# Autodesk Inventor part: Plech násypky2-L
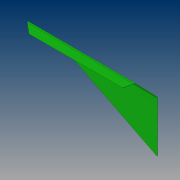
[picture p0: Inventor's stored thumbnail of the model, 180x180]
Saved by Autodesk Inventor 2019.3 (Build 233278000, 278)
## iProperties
Created: 2019-02
Part Number: Plech násypky2-L
Material: Ocel, legovaná
Document SubType Name: Plech
Designer: B-hon
Density: 7.73 g/cm^3
Sheet Metal Rule: Výchozí_mm
Appearance: Tmavě zelená
Author: B-hon
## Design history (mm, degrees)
node "Plocha1"
  sketch "Náčrt1"
    geometry: L1 (0, 0)-(380, 0); L2 (380, 0)-(380, 399.046); L3 (380, 399.046)-(0, 399.046); L4 (0, 399.046)-(0, 0)
    constraints: 8 end point, 2 parallel, 1 horizontal, 1 perpendicular
    dimensions: "d0" = 380 distance of L3.end L2.end
node "Obruba3"
sketch "Náčrt9"
  geometry: L1 (0, 0)-(380, 0) reference; L2 (380, 0)-(355.9, -113.384); L3 (0, -113.384)-(380, -113.384) reference; L4 (380, 0)-(380, -113.384) reference; 1 further point
  constraints: 2 end point, 1 point on line
  dimensions: "d55" = 12 deg angle of L4 L2
extrude "Vysunutí5" cut sketch "Náčrt9" distance "d56" = 10; taper "d57" = 0 deg
sketch "Náčrt10"
  geometry: L1 (-24.1, 400.209)-(0, 400.209) reference; L2 (-380, 400.209)-(-24.1, 400.209) reference; L3 (-24.1, 400.209)-(-510.684, 153.671); L4 (-510.205, 151.672)-(-426.211, -198.903); L5 (-426.211, -198.903)-(304.747, -58.027); L6 (304.747, -58.027)-(0, 400.209); L7 (-510.205, 151.672)-(-19.675, 400.209); 1 further point
  constraints: 10 end point, 1 parallel, 1 point on line
  dimensions: "d58" = 26.87 deg angle of L2 L3; "d83" = 2 distance between parallel lines of L3 L7
node "Upravit přímo3"
node "Upravit přímo4"
node "Obruba4"
extrude "Vysunutí8" cut sketch "Náčrt10" distance "d84" = 10; taper "d85" = 0 deg
node "Upravit přímo5"
node "Upravit přímo6"
sketch "Náčrt12"
  geometry: L1 (0, 0)-(0, 23); L2 (0, 21)-(0, 0) reference; L3 (352.406, 0)-(0, 0) reference; L4 (352.406, 0)-(352.406, 13.732); L5 (352.406, 21)-(352.406, 0) reference; L6 (371.519, 32.844)-(331.383, -7.291); L7 (331.383, -7.291)-(388.224, -9.134); L8 (388.224, -9.134)-(371.519, 32.844); L9 (-7.536, 30.536)-(34.31, -11.31); L10 (34.31, -11.31)-(-10.239, -14.013); L11 (-10.239, -14.013)-(-7.536, 30.536); L12 (0.85, 25)-(361.674, 25) reference; L13 (361.674, 21)-(361.674, 25) reference; 2 further points
  constraints: 16 end point, 3 point on line, 2 collinear, 1 midpoint
  dimensions: "d77" = 23 distance of L1.start L1.end; "d79" = 45 deg angle of L3 L9; "d80" = 45 deg angle of L3 L6; "d92" = 2 distance from line of L12 point (361.674, 23)
extrude "Vysunutí9" cut sketch "Náčrt12" distance "d93" = 6; taper "d94" = 0 deg
node "Těleso1"
feature "Deska1" dims "d1" = 2 (= Tloušťka)
sketch "Náčrt8"
  geometry: L1 through (-190, 0) direction (1, 0); L2 through (0, 57.5) direction (0, 1); L3 (0, 115)-(-380, 115); L4 (-380, 115)-(-380, 0)
  constraints: 6 end point, 1 horizontal, 1 perpendicular, 1 vertical
feature "Deska4" dims "d1" = 2 (= Tloušťka), "d45" = 2 (= ŠířkaVýštipu), "d46" = 1 (= HloubkaVýštipu), "d47" = 4 (= MinimálníZbytek), "d48" = 2 (= PřechodovýPoloměr), "d49" = 115, "d50" = 44 deg, "d51" = 2 (= PoloměrOhybu), "d52" = 8 (= VelikostRohovéhoVýštipu), "d53" = 2 (= VelikostMezery), "d54" = 2 (= VelikostJacobihoPoloměru), "MezeraVystřižení" = 0.01
feature "Ohyb3" dims "d1" = 2 (= Tloušťka), "d45" = 2 (= ŠířkaVýštipu), "d46" = 1 (= HloubkaVýštipu), "d47" = 4 (= MinimálníZbytek), "d48" = 2 (= PřechodovýPoloměr), "d49" = 115, "d50" = 44 deg, "d51" = 2 (= PoloměrOhybu), "MezeraVystřižení" = 0.01
feature "Roh3" dims "d49" = 115, "d50" = 44 deg, "d52" = 8 (= VelikostRohovéhoVýštipu), "d53" = 2 (= VelikostMezery), "d54" = 2 (= VelikostJacobihoPoloměru)
sketch "Náčrt11"
  geometry: L1 through (-176.203, 0) direction (1, 1.51e-18); L2 through (0, 12.5) direction (-1.51e-18, 1); L3 (0, 25)-(-352.406, 25); L4 (-352.406, 25)-(-352.406, 0)
  constraints: 6 end point, 1 horizontal, 1 perpendicular, 1 vertical
feature "Deska5" dims "d1" = 2 (= Tloušťka), "d67" = 2 (= ŠířkaVýštipu), "d68" = 1 (= HloubkaVýštipu), "d69" = 4 (= MinimálníZbytek), "d70" = 2 (= PřechodovýPoloměr), "d71" = 25, "d72" = 90 deg, "d73" = 2 (= PoloměrOhybu), "d74" = 8 (= VelikostRohovéhoVýštipu), "d75" = 2 (= VelikostMezery), "d76" = 2 (= VelikostJacobihoPoloměru), "MezeraVystřižení" = 0.01
feature "Ohyb4" dims "d1" = 2 (= Tloušťka), "d67" = 2 (= ŠířkaVýštipu), "d68" = 1 (= HloubkaVýštipu), "d69" = 4 (= MinimálníZbytek), "d70" = 2 (= PřechodovýPoloměr), "d71" = 25, "d72" = 90 deg, "d73" = 2 (= PoloměrOhybu), "MezeraVystřižení" = 0.01
feature "Roh4" dims "d71" = 25, "d72" = 90 deg, "d74" = 8 (= VelikostRohovéhoVýštipu), "d75" = 2 (= VelikostMezery), "d76" = 2 (= VelikostJacobihoPoloměru)
feature "Posunout3" dims "d63" = -2.43
feature "Posunout4" dims "d66" = -27.077
feature "Posunout5" dims "d88" = -4.5
feature "Posunout6" dims "d91" = 9.268
other parameters: "Tloušťka" = 2 (derived), "KSoučinitel" = 4.4, "PoloměrOhybu" = 2 (= Tloušťka), "ŠířkaVýštipu" = 2 (= Tloušťka), "HloubkaVýštipu" = 1 (= 0.5 x Tloušťka), "VelikostRohovéhoVýštipu" = 8 (= 4 x Tloušťka), "MinimálníZbytek" = 4 (= 2 x Tloušťka), "PřechodovýPoloměr" = 2 (= PoloměrOhybu), "VelikostJacobihoPoloměru" = 2 (= PoloměrOhybu), "VelikostMezery" = 2 (= Tloušťka), "d61" = 0, "d62" = 0, "d64" = 0, "d65" = 0, "d86" = 0, "d87" = 0, "d89" = 0, "d90" = 0
